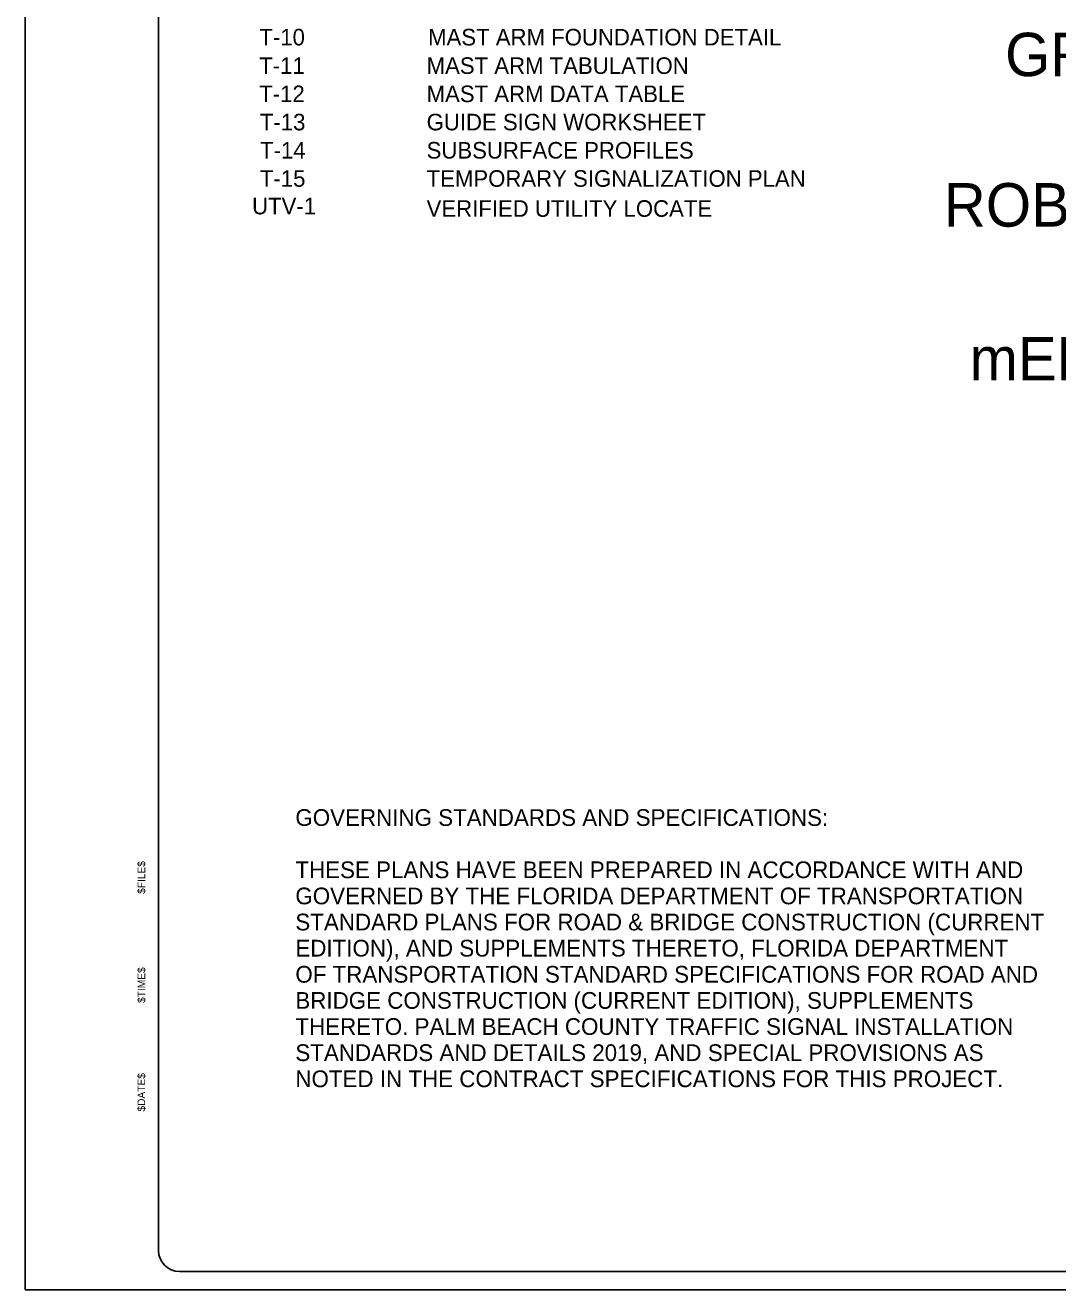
# Model space of a CAD drawing. Extents: x 801329 to 1085229, y 842463 to 1044570.
# Drawn here: x 801329 to 885326, y 842463 to 945308 of the extents above; entities that cross this region are included whole.
import ezdxf

# ---------------------------------------------------------------- set-up
doc = ezdxf.new("R2010")
doc.units = 0
for name, color, linetype in [('Default', 7, 'Continuous'), ('PlotBorder_dp', 7, 'Continuous'), ('TextLabel', 7, 'Continuous')]:
    doc.layers.add(name, color=color, linetype=linetype)

msp = doc.modelspace()

# ---------------------------------------------------------------- linework, layer by layer
at = {"layer": 'Default'}
for p, q in [((812167, 845650), (812167, 1016925)), ((1063315, 843950), (813867, 843950))]:
    msp.add_line(p, q, dxfattribs=at)
msp.add_arc((813867, 845650), 1700, 180, 270, dxfattribs=at)
at = {"layer": 'PlotBorder_dp'}
msp.add_lwpolyline([(801329, 842463), (1085229, 842463), (1085229, 1022663), (801329, 1022663)], close=True, dxfattribs=at)

# ---------------------------------------------------------------- texts
at = {"layer": 'Default'}
for s, height, p in [('  T-10   ', 1348.1, (819371, 943671)), ('MAST ARM FOUNDATION DETAIL', 1347.67, (834102, 943671)), ('  T-11   ', 1348.1, (819359, 941353)), ('MAST ARM TABULATION                ', 1347.67, (833980, 941353)), ('  T-12   ', 1348.1, (819355, 939058)), ('MAST ARM DATA TABLE                ', 1347.67, (833980, 939058)), ('  T-13   ', 1348.1, (819412, 936763)), ('GUIDE SIGN WORKSHEET               ', 1347.67, (833980, 936763)), ('  T-14   ', 1348.1, (819426, 934468)), ('SUBSURFACE PROFILES                ', 1347.67, (833980, 934468)), ('  T-15   ', 1348.1, (819415, 932173)), ('TEMPORARY SIGNALIZATION PLAN       ', 1347.67, (833980, 932173)), ('  UTV-1  ', 1348.1, (818779, 929933)), ('VERIFIED UTILITY LOCATE            ', 1347.67, (833980, 929730)), ('GOVERNING STANDARDS AND SPECIFICATIONS:', 1360, (823302, 880188)), ('THESE PLANS HAVE BEEN PREPARED IN ACCORDANCE WITH AND', 1360, (823302, 875938)), ('GOVERNED BY THE FLORIDA DEPARTMENT OF TRANSPORTATION', 1360, (823302, 873813)), ('STANDARD PLANS FOR ROAD & BRIDGE CONSTRUCTION (CURRENT', 1360, (823302, 871688)), ('EDITION), AND SUPPLEMENTS THERETO, FLORIDA DEPARTMENT ', 1360, (823302, 869563)), ('OF TRANSPORTATION STANDARD SPECIFICATIONS FOR ROAD AND ', 1360, (823302, 867438)), ('BRIDGE CONSTRUCTION (CURRENT EDITION), SUPPLEMENTS ', 1360, (823302, 865313)), ('THERETO. PALM BEACH COUNTY TRAFFIC SIGNAL INSTALLATION ', 1360, (823302, 863188)), ('STANDARDS AND DETAILS 2019, AND SPECIAL PROVISIONS AS ', 1360, (823302, 861063)), ('NOTED IN THE CONTRACT SPECIFICATIONS FOR THIS PROJECT.', 1360, (823302, 858938))]:
    msp.add_text(s, height=height, dxfattribs=at).set_placement(p)
for s, p in [('$FILE$', (811084, 874655)), ('$TIME$', (811091, 865787)), ('$DATE$', (811082, 856952))]:
    msp.add_text(s, height=619.5, rotation=90, dxfattribs=at).set_placement(p)
at = {"layer": 'TextLabel'}
for s, height, p in [('GREGG K. WEISS', 3531.23, (881043, 941169)), ('ROBERT S. WEINROTH', 3544.29, (876054, 928929)), ('mELISSA mCkINLAY', 3531.23, (878159, 916417))]:
    msp.add_text(s, height=height, rotation=360, dxfattribs=at).set_placement(p)

doc.saveas('drawing.dxf')
